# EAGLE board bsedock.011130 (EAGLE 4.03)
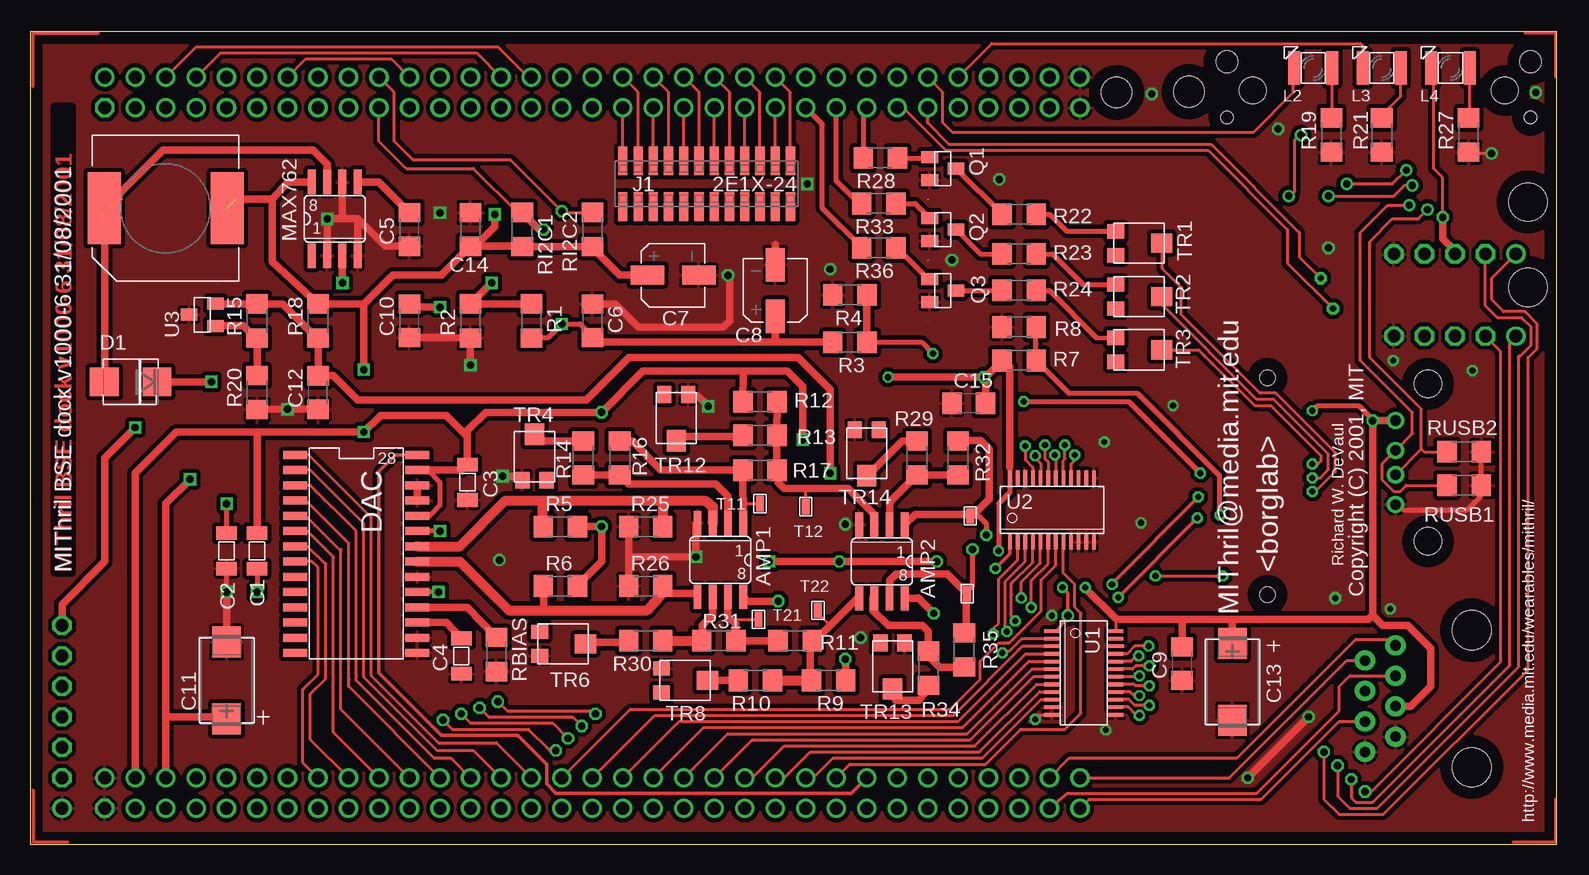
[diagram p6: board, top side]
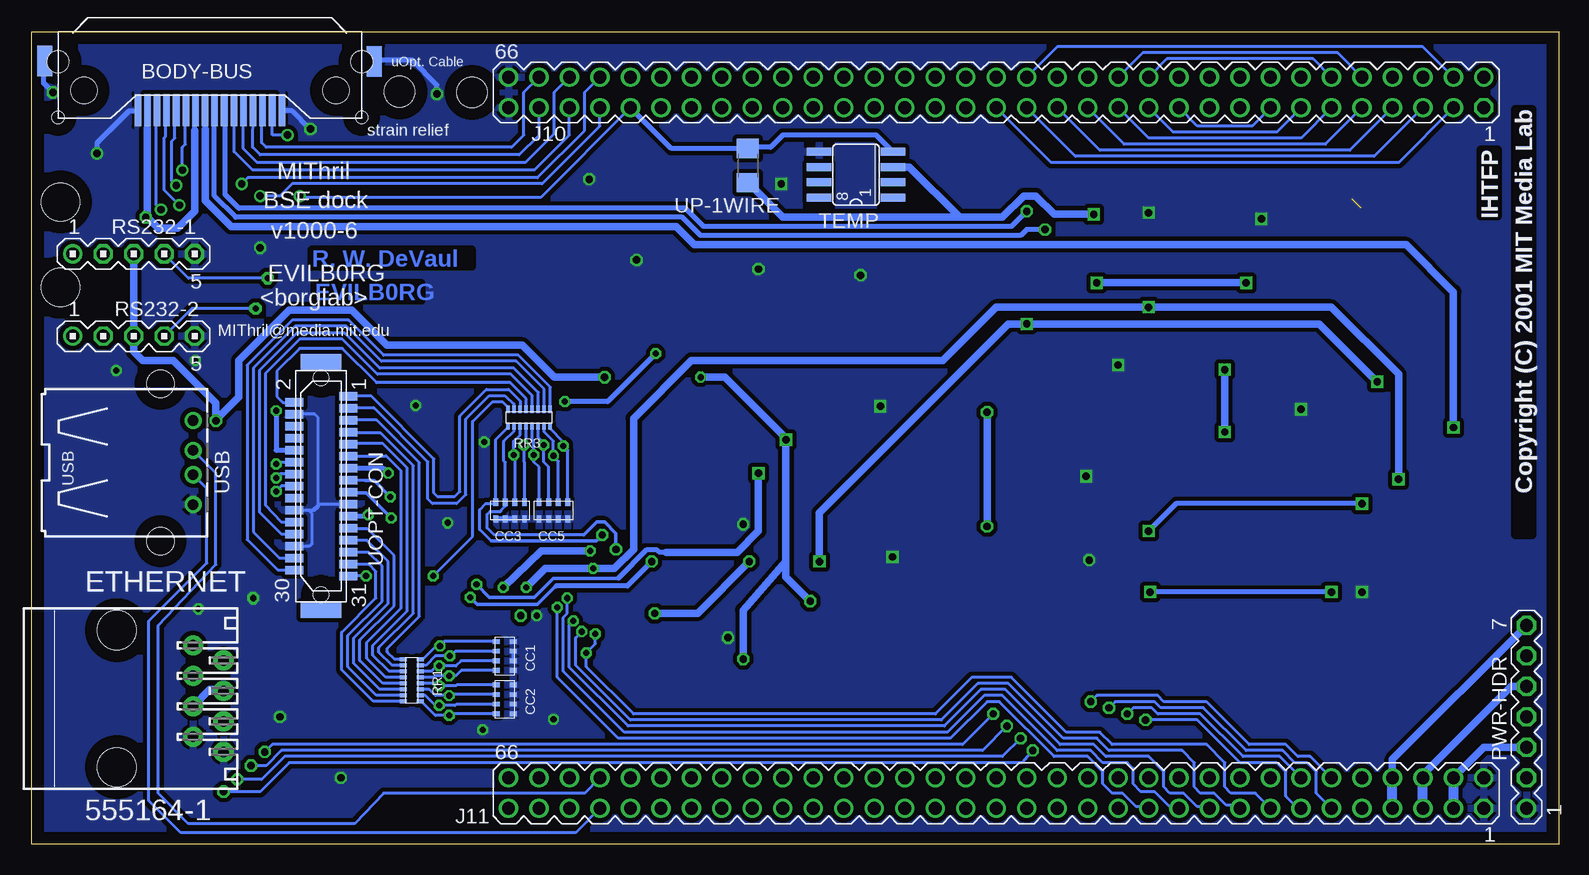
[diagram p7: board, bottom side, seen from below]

Size 127.23 x 67.74 mm. Coordinates in mm from the lower left corner, seen from the top.
Outline: 0,0 127.23,0 127.23,67.74 0,67.74 0,0
Copper layers used: Top, Bottom
Holes 3.17 mm at 124.84,46.44 124.84,53.56
Holes 2.54 mm at 90.55,62.7 96.58,62.76

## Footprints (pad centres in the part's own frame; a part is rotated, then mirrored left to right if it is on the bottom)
SO08 = smd 0.66 x 2.032: 1 -1.905,-3.073; 2 -0.635,-3.073; 3 0.635,-3.073; 4 1.905,-3.073; 5 1.905,3.073; 6 0.635,3.073; 7 -0.635,3.073; 8 -1.905,3.073
HRS3500 = smd 0.55 x 2.7: P$1 6,1.35; P$2 5.2,1.35; P$3 4.4,1.35; P$4 3.6,1.35; P$5 2.8,1.35; P$6 2,1.35; P$7 1.2,1.35; P$8 0.4,1.35; P$9 -0.4,1.35; P$10 -1.2,1.35; P$11 -2,1.35; P$12 -2.8,1.35; P$13 -3.6,1.35; P$14 -4.4,1.35; P$15 -5.2,1.35; P$16 -6,1.35 | smd 1.27 x 2.54: P_GND1 -13.7,-2.7; P_GND2 13.76,-2.74 | hole 2.2: -10.5,-0.3; 10.5,-0.3 | hole 1.8: -12.65,-2.7; 12.65,-2.7 | hole 1: -12.65,1.95; 12.65,1.95
1206 = smd 1.143 x 1.702: 1 -1.473,0; 2 1.473,0
C1206 = smd 1.6 x 1.8: 1 -1.4,0; 2 1.4,0
PAN-LY-C = smd 1.6 x 2.8: P+ 0,-2.15; P- 0,2.15
CT7343 = smd 2.6 x 2.4: 1 -3.2,0; 2 3.2,0
ECJRV = smd 0.4 x 0.6: P$1 -1.2,-0.7; P$2 -0.4,-0.7; P$3 0.4,-0.7; P$4 1.2,-0.7; P$5 1.2,0.7; P$6 0.4,0.7; P$7 -0.4,0.7; P$8 -1.2,0.7
SMB = smd 2.4 x 2.4: 1 -2.2,0; 2 2.2,0
SMD-28 = smd 0.66 x 2.007: 1 -8.89,-5.08; 2 -7.62,-5.08; 3 -6.35,-5.08; 4 -5.08,-5.08; 5 -3.81,-5.08; 6 -2.54,-5.08; 7 -1.27,-5.08; 8 0,-5.08; 9 1.27,-5.08; 10 2.54,-5.08; 11 3.81,-5.08; 12 5.08,-5.08; 13 6.35,-5.08; 14 7.62,-5.08; 15 7.62,5.08; 16 6.35,5.08; 17 5.08,5.08; 18 3.81,5.08; 19 2.54,5.08; 20 1.27,5.08; 21 0,5.08; 22 -1.27,5.08; 23 -2.54,5.08; 24 -3.81,5.08; 25 -5.08,5.08; 26 -6.35,5.08; 27 -7.62,5.08; 28 -8.89,5.08
555164-1 = drill 0.889 pad 1.676 round: 1 -4.445,5.207; 2 -3.175,7.747; 3 -1.905,5.207; 4 -0.635,7.747; 5 0.635,5.207; 6 1.905,7.747; 7 3.175,5.207; 8 4.445,7.747 | hole 3.251: -5.715,-1.143; 5.715,-1.143
2E1X-24 = smd 0.762 x 2.388: P$1 -7.62,1.905; P$2 -7.62,-1.905; P$3 -6.35,1.905; P$4 -6.35,-1.905; P$5 -5.08,1.905; P$6 -5.08,-1.905; P$7 -3.81,1.905; P$8 -3.81,-1.905; P$9 -2.54,1.905; P$10 -2.54,-1.905; P$11 -1.27,1.905; P$12 -1.27,-1.905; P$13 0,1.905; P$14 0,-1.905; P$15 1.27,1.905; P$16 1.27,-1.905; P$17 2.54,1.905; P$18 2.54,-1.905; P$19 3.81,1.905; P$20 3.81,-1.905; P$21 5.08,1.905; P$22 5.08,-1.905; P$23 6.35,1.905; P$24 6.35,-1.905
BSEHDR = drill 1.067 pad 1.6 octagon: 1 -41.91,-1.27 | drill 1.067 pad 1.6 round: 2 -41.91,1.27; 3 -39.37,-1.27; 4 -39.37,1.27; 5 -36.83,-1.27; 6 -36.83,1.27; 7 -34.29,-1.27; 8 -34.29,1.27; 9 -31.75,-1.27; 10 -31.75,1.27; 11 -29.21,-1.27; 12 -29.21,1.27; 13 -26.67,-1.27; 14 -26.67,1.27; 15 -24.13,-1.27; 16 -24.13,1.27; 17 -21.59,-1.27; 18 -21.59,1.27; 19 -19.05,-1.27; 20 -19.05,1.27; 21 -16.51,-1.27; 22 -16.51,1.27; 23 -13.97,-1.27; 24 -13.97,1.27; 25 -11.43,-1.27; 26 -11.43,1.27; 27 -8.89,-1.27; 28 -8.89,1.27; 29 -6.35,-1.27; 30 -6.35,1.27; 31 -3.81,-1.27; 32 -3.81,1.27; 33 -1.27,-1.27; 34 -1.27,1.27; 35 1.27,-1.27; 36 1.27,1.27; 37 3.81,-1.27; 38 3.81,1.27; 39 6.35,-1.27; 40 6.35,1.27; 41 8.89,-1.27; 42 8.89,1.27; 43 11.43,-1.27; 44 11.43,1.27; 45 13.97,-1.27; 46 13.97,1.27; 47 16.51,-1.27; 48 16.51,1.27; 49 19.05,-1.27; 50 19.05,1.27; 51 21.59,-1.27; 52 21.59,1.27; 53 24.13,-1.27; 54 24.13,1.27; 55 26.67,-1.27; 56 26.67,1.27; 57 29.21,-1.27; 58 29.21,1.27; 59 31.75,-1.27; 60 31.75,1.27; 61 34.29,-1.27; 62 34.29,1.27; 63 36.83,-1.27; 64 36.83,1.27; 65 39.37,-1.27; 66 39.37,1.27
D124C = smd 2.743 x 5.994: P$1 -5.131,0; P$2 5.131,0
L62711CT = smd 1 x 2.8: P$1 -1.6,0; P$2 1.6,0
MA07-1 = drill 1.067 pad 1.6 round: 1 -7.62,0 | drill 1.067 pad 1.6 octagon: 2 -5.08,0; 3 -2.54,0; 4 0,0; 5 2.54,0; 6 5.08,0; 7 7.62,0
SOT23 = smd 1 x 1.4: 1 -0.95,-1.1; 2 0.95,-1.1; 3 0,1.1
R1206 = smd 1.6 x 1.803: 1 -1.422,0; 2 1.422,0
EXB2HV = smd 0.294 x 0.6: P$1 -1.75,-0.7; P$2 -1.25,-0.7; P$3 -0.75,-0.7; P$4 -0.25,-0.7; P$5 0.25,-0.7; P$6 0.75,-0.7; P$7 1.25,-0.7; P$8 1.75,-0.7; P$9 1.75,0.7; P$10 1.25,0.7; P$11 0.75,0.7; P$12 0.25,0.7; P$13 -0.25,0.7; P$14 -0.75,0.7; P$15 -1.25,0.7; P$16 -1.75,0.7
MA05-1 = drill 1.067 pad 1.6 round: 1 -5.08,0 | drill 1.067 pad 1.6 octagon: 2 -2.54,0; 3 0,0; 4 2.54,0; 5 5.08,0
TEST = smd 0.66 x 1.27: P$1 0,0
P7JSMTPO = smd 1.194 x 1.397: 1 -1,-1.854; 3 1,-1.854 | smd 1.6 x 1.778: 2 0,1.98
QSOP24 = smd 0.305 x 1.27: P$1 0.838,-0.711; P$2 1.473,-0.711; P$3 2.108,-0.711; P$4 2.743,-0.711; P$5 3.378,-0.711; P$6 4.013,-0.711; P$7 4.648,-0.711; P$8 5.283,-0.711; P$9 5.918,-0.711; P$10 6.553,-0.711; P$11 7.188,-0.711; P$12 7.823,-0.711; P$13 7.823,4.623; P$14 7.188,4.623; P$15 6.553,4.623; P$16 5.918,4.623; P$17 5.283,4.623; P$18 4.648,4.623; P$19 4.013,4.623; P$20 3.378,4.623; P$21 2.743,4.623; P$22 2.108,4.648; P$23 1.473,4.623; P$24 0.838,4.623
DF9-31S = smd 0.7 x 1.5: 1 -7.5,2.25; 2 -7,-2.25; 3 -6.5,2.25; 4 -6,-2.25; 5 -5.5,2.25; 6 -5,-2.25; 7 -4.5,2.25; 8 -4,-2.25; 9 -3.5,2.25; 10 -3,-2.25; 11 -2.5,2.25; 12 -2,-2.25; 13 -1.5,2.25; 14 -1,-2.25; 15 -0.5,2.25; 16 0,-2.25; 17 0.5,2.25; 18 1,-2.25; 19 1.5,2.25; 20 2,-2.25; 21 2.5,2.25; 22 3,-2.25; 23 3.5,2.25; 24 4,-2.25; 25 4.5,2.25; 26 5,-2.25; 27 5.5,2.25; 28 6,-2.25; 29 6.5,2.25; 30 7,-2.25; 31 7.5,2.25 | smd 1.3 x 3.4: M1 -10.35,0; M2 10.35,0 | hole 1.27: 9.05,0; -9.05,0
USB = drill 0.889 pad 1.422 round: 1 -3.505,12.7; 2 -1.016,12.7; 3 1.016,12.7; 4 3.505,12.7 | hole 2.261: -6.566,9.982; 6.566,9.982

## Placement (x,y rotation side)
AMP1  AD8042AR  [SO08]  57.53,23.71 180 top
AMP2  EL2250CS  [SO08]  70.99,23.58 180 top
BODY-BUS  HRS3500R  [HRS3500]  112.39,62.57 180 bottom
C1  0.1uF  [1206]  18.92,24.47 90 top
C2  0.1uF  [1206]  16.38,24.47 270 top
C3  0.1uF  [1206]  36.44,30.19 270 top
C4  0.1uF  [1206]  35.94,15.71 270 top
C5  0.1uF  [C1206]  31.62,51.27 90 top
C6  0.1uF  [C1206]  46.86,43.65 270 top
C7  33uF  [PAN-LY-C]  53.59,47.46 270 top
C8  33uF  [PAN-LY-C]  62.1,46.19 0 top
C9  0.1uF  [C1206]  96.01,15.07 90 top
C10  0.1uF  [C1206]  31.62,43.65 90 top
C11  10uF  [CT7343]  16.38,13.68 90 top
C12  0.1uF  [C1206]  24,37.68 90 top
C13  10uF  [CT7343]  100.2,13.55 270 top
C14  0.1uF  [C1206]  36.7,51.27 270 top
C15  0.1uF  [C1206]  78.23,36.79 0 top
CC1  10pF  [ECJRV]  87.82,15.71 90 bottom
CC2  10pF  [ECJRV]  87.82,12.09 90 bottom
CC3  10pF  [ECJRV]  87.37,27.84 0 bottom
CC5  10pF  [ECJRV]  83.75,27.84 0 bottom
D1  MBRS130LT3  [SMB]  8.38,38.57 180 top
DAC  THS5641IDW  [SMD-28]  27.17,23.58 270 top
ETHERNET  555164-1  [555164-1]  118.99,12.15 270 bottom
J1  2E1X-24  [2E1X-24]  57.02,55.08 0 top
J10  BSEHDR  [BSEHDR]  48.13,62.7 0 top
J11  BSEHDR  [BSEHDR]  48.13,4.28 0 top
L1  [D124C]  11.3,53.05 180 top
L2  L628111CT-ND  [L62711CT]  106.93,64.73 0 top
L3  L628111CT-ND  [L62711CT]  112.64,64.73 0 top
L4  L628111CT-ND  [L62711CT]  118.36,64.73 0 top
MAX762  MAX762  [SO08]  25.39,52.16 0 top
PWR-HDR  MA07-1  [MA07-1]  2.66,10.63 90 bottom
Q1  2N7002  [SOT23]  76.07,56.35 270 top
Q2  2N7002  [SOT23]  76.07,51.27 270 top
Q3  2N7002  [SOT23]  76.07,46.19 270 top
R1  1.267M  [R1206]  41.78,43.65 270 top
R2  200K  [R1206]  36.7,43.65 90 top
R3  16.4k  [R1206]  68.32,41.87 180 top
R4  23.6k  [R1206]  68.32,45.81 0 top
R5  2.65k  [R1206]  44.19,26.51 0 top
R6  2.65k  [R1206]  44.19,21.55 0 top
R7  20K  [R1206]  82.42,40.35 180 top
R8  20K  [R1206]  82.42,43.14 0 top
R9  2.52k  [R1206]  66.54,13.68 0 top
R10  2.0k  [R1206]  60.45,13.68 0 top
R11  2.90k  [R1206]  63.75,16.98 180 top
R12  7.06k  [R1206]  60.83,36.92 180 top
R13  2.0k  [R1206]  60.83,34.12 0 top
R14  2k  [R1206]  46.1,32.22 270 top
R15  43k  [R1206]  18.92,43.65 90 top
R16  3.78k  [R1206]  49.14,32.22 90 top
R17  4.05k  [R1206]  60.83,31.2 180 top
R18  47k  [R1206]  24,43.65 90 top
R19  2.2k  [R1206]  108.45,59.14 90 top
R20  30k  [R1206]  18.92,37.68 90 top
R21  2.2k  [R1206]  112.64,59.14 90 top
R22  10 ohm  [R1206]  82.42,52.54 180 top
R23  10 ohm  [R1206]  82.42,49.24 180 top
R24  10 ohm  [R1206]  82.42,46.19 180 top
R25  49  [R1206]  51.3,26.51 0 top
R26  49  [R1206]  51.3,21.55 0 top
R27  2.2k  [R1206]  119.88,59.14 90 top
R28  10 ohm  [R1206]  70.86,57.24 180 top
R29  2k  [R1206]  73.91,32.22 270 top
R30  2k  [R1206]  51.3,16.98 0 top
R31  3.78k  [R1206]  57.4,16.98 0 top
R32  6.3k  [R1206]  77.34,32.22 90 top
R33  10 ohm  [R1206]  70.73,53.43 180 top
R34  2k  [R1206]  74.86,14.69 90 top
R35  6.3k  [R1206]  77.85,16.22 90 top
R36  10 ohm  [R1206]  70.73,49.75 180 top
RBIAS  2k  [R1206]  38.86,15.84 90 top
RI2C1  5k  [R1206]  41.02,51.27 270 top
RI2C2  5k  [R1206]  46.86,51.27 270 top
RR1  10  [EXB2HV]  95.56,13.68 90 bottom
RR3  10  [EXB2HV]  85.78,35.59 0 bottom
RS232-1  [MA05-1]  118.74,49.24 180 top
RS232-2  [MA05-1]  118.74,42.38 180 top
RUSB1  15K  [R1206]  119.5,29.93 180 top
RUSB2  15K  [R1206]  119.5,32.73 180 top
T1  TEST  [TEST]  60.83,28.41 0 top
T2  TEST  [TEST]  60.7,18.76 0 top
T3  TEST  [TEST]  65.65,19.52 0 top
T4  TEST  [TEST]  64.64,28.16 0 top
T5  TEST  [TEST]  78.35,27.39 0 top
T6  TEST  [TEST]  78.1,20.92 0 top
TEMP  DS1820  [SO08]  58.54,55.84 90 bottom
TR1  200 POT  [P7JSMTPO]  92.32,50.13 270 top
TR2  200 POT  [P7JSMTPO]  92.32,45.68 270 top
TR3  200 POT  [P7JSMTPO]  92.32,41.24 270 top
TR4  200 POT  [P7JSMTPO]  42.03,32.22 0 top
TR6  200 POT  [P7JSMTPO]  44.32,16.73 270 top
TR8  200 POT  [P7JSMTPO]  54.48,13.68 270 top
TR12  200 POT  [P7JSMTPO]  53.84,35.65 180 top
TR13  200 POT  [P7JSMTPO]  71.88,14.95 180 top
TR14  200 POT  [P7JSMTPO]  69.72,32.73 180 top
U1  74LVX3245QSCF  [QSOP24]  85.85,18.63 270 top
U2  74LVX3245QSCF  [QSOP24]  80.83,25.93 0 top
U3  [SOT23]  14.35,44.16 90 top
UOPT-CON  DF9-31P-1V  [DF9-31S]  103.12,29.87 270 bottom
UP-1WIRE  5k  [R1206]  67.56,56.6 270 bottom
USB  USB-87531  [USB]  126.49,31.84 270 bottom

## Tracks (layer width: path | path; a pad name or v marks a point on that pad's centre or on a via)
1WIRE  (via drill 0.61 pad 1.02)
  Top 0.254: v105.91,59.14 105.79,59.14 105.41,58.76 105.41,54.45 105.02,54.06 v104.9,54.06
  Bottom 0.254: v105.91,59.14 107.18,59.14 BODY-BUS.P$15 | v104.9,54.06 105.02,53.94 84.83,53.94 J10.57
  Bottom 0.406: J10.57 73.93,58.03 UP-1WIRE.1 67.46,58.13 65.65,58.13 64.64,59.14 56.87,59.14 TEMP.4
+2V  (via drill 0.51 pad 0.3, 0.61 pad 1.02)
  Top 0.305: v97.34,28.98 90.17,21.74 v90.17,21.68
  Top 0.61: v66.67,30.95 66.67,37.93 64,40.6 49.91,40.6 46.35,37.05 27.3,37.05 25.27,39.08 C12.2 R18.1 23.9,42.23 21.08,45.05 18.92,45.05 R15.2 18.89,45.05 15.49,45.05 15.49,45.06 U3.2
  Bottom 0.305: 78.35,22.19 83.75,22.19 85.34,20.6 89.09,20.6 v90.17,21.68 | UOPT-CON.15 99.44,30.34 98.7,30.34 v97.34,28.98
  Bottom 0.406: 74.35,24.35 74.92,24.35 75.12,24.54 76.01,24.54 78.35,22.19
  Bottom 0.61: v66.67,30.95 66.67,26.12 68.45,24.35 74.35,24.35
+3V  (via drill 0.51 pad 0.3, 0.61, 0.61 pad 1.02)
  Top 0.254: 81.66,25.23 U2.P$1
  Top 0.305: U1.P$1 85.58,17.79 v86.48,19.08 86.48,20.98 v86.04,21.42 | v80.45,23.01 81.66,24.22 81.66,25.23
  Top 0.61: J11.6 11.3,10.63 | 11.3,10.63 11.3,28.41 v13.33,30.44 | v34.16,44.79 32.76,44.79 C10.2 | C11.1 16.38,10.63 11.3,10.63
  Bottom 0.61: v13.33,30.44 13.33,39.2 18.92,44.79 v34.16,44.79 46.86,44.79 51.3,40.35 72.26,40.35 77.08,35.52 77.08,24.6 78.67,23.01 v80.45,23.01 84.45,23.01 v86.04,21.42 | PWR-HDR.5 3.93,13.17 11.3,5.8 J11.6
  Bottom 0.813: J11.5 J11.6
+5V  (via drill 0.51 pad 0.3, 0.61, 0.61 pad 1.02)  (1 unrouted)
  Top 0.254: 116.84,64.66 L4.P$1 116.76,64.28 116.71,64.22 116.71,64.48 116.96,64.22 116.96,56.35 117.72,55.59 v117.72,52.29 | v87.94,21.42 87.94,21.36 | 90.47,18.83 U1.P$24 | 81.66,30.57 U2.P$24 | RS232-1.3 118.74,49.49
  Top 0.305: 81.02,40.35 81.02,40.48 81.66,39.84
  Top 0.406: DAC.24 33.27,27.39 34.16,28.28 34.16,30.19 33.14,31.2 DAC.27 32.13,31.2 | 81.66,31.46 81.66,30.57 81.66,29.36 80.7,28.41 v80.7,24.47 | v106.87,36.16 107.25,36.54 110.75,36.54 111.88,35.41 111.9,35.39 | 90.8,18.76 90.55,18.76
  Top 0.61: ETHERNET.5 115.06,11.52 116.71,13.17 116.71,16.34 114.8,18.25 112.71,18.25 111.88,19.08 111.88,19.14 | 59.43,39.46 51.05,39.46 v47.62,36.03 37.97,36.03 36.44,34.51 36.44,34 | 59.43,39.46 63.11,39.46 64.38,38.19 v64.38,33.74 | 18.92,34.38 v27.81,34.38 29.2,35.78 34.67,35.78 36.44,34 | C14.2 34.28,47.46 30.22,47.46 27.81,45.05 | 27.81,45.05 24,45.05 | MAX762.8 23.52,55.21 21.46,55.21 20.19,53.81 | C14.2 39.11,49.87 40.25,49.87 RI2C1.2 RI2C2.2 | R5.2 v47.62,26.51 47.62,23.58 R6.2 | 59.43,39.46 R12.2 | R9.2 68.07,13.14 v67.94,15.46 | RI2C2.2 46.86,49.87 | 24,45.05 R18.2 | 24,45.05 20.19,48.6 20.19,53.81 | 20.19,53.81 17.19,53.81 | DAC.27 35.94,31.2 36.44,31.71 C3.1 36.44,34 | J11.4 8.76,30.95 12.19,34.38 18.92,34.38 | v27.81,39.59 27.81,45.05 | 18.92,34.38 C1.2 | RI2C2.2 46.86,49.75 49.14,47.46 C7.P+ | v38.73,52.54 38.73,51.52 37.21,50 36.7,50 C14.2 | v117.72,52.29 117.72,50.51 118.74,49.49 | v62.35,20.28 59.56,20.28 59.56,20.54 59.46,20.64 AMP1.8 | R7.2 81.02,40.35 79.62,38.95 v79.5,38.95 | v71.5,38.95 v79.5,38.95 | 81.66,39.84 81.66,31.46 | 111.88,33.36 111.88,19.14 | 111.88,33.36 111.88,33.38 | v111.88,35.33 111.88,33.36 | v111.88,35.33 111.88,35.41 | USB.1 v111.88,35.33 | C15.2 79.63,38.82 v79.5,38.95 | 100.2,18.76 C13.1 | 96.01,18.76 C9.2 | 100.2,18.76 111.5,18.76 111.88,19.14 | 87.94,21.36 90.47,18.83 | 96.01,18.76 90.8,18.76 | 100.2,18.76 96.01,18.76
  Bottom 0.254: v64.38,33.74 64.32,33.81
  Bottom 0.406: 117.6,59.71 BODY-BUS.P$2 | v117.72,52.29 117.6,52.29 | BODY-BUS.P$7 113.64,61.18 113.66,61.18 113.66,59.52 | UOPT-CON.10 106.72,32.87 106.87,32.85 v106.87,36.16
  Bottom 0.61: v64.38,33.74 64.38,23.58 | v27.81,34.38 v27.81,39.59 | v47.62,36.03 v47.62,26.51 | 117.6,59.71 117.6,52.29 116.71,51.4 115.06,51.4 113.66,52.79 113.66,59.52 | v67.94,15.46 67.94,19.52 64.38,23.58 | v38.73,52.54 42.03,52.54 43.56,54.06 44.57,54.06 46.35,52.29 49.91,52.29 | 49.91,52.29 64.64,52.29 67.43,55.08 67.46,55.08 UP-1WIRE.2 | ETHERNET.4 111.37,12.92 112.39,12.92 ETHERNET.5 | RS232-1.3 RS232-2.3 118.74,41.11 117.98,40.35 115.44,40.35 111.88,36.79 111.88,35.39 | 64.38,23.58 64.38,22.31 v62.35,20.28 | TEMP.3 54.1,56.48 49.91,52.29 | J11.4 6.22,8.09 PWR-HDR.3 | v80.7,24.47 84.77,24.47 v87.94,21.42 | v71.5,38.95 69.46,38.95 64.32,33.81 | 111.88,35.39 v111.88,35.33 | v79.5,38.95 83.69,38.95 86.36,41.62 97.66,41.62 100.58,44.54 105.79,44.54 109.98,40.35 109.98,37.3 111.88,35.39
  Bottom 0.813: J11.4 J11.3
+6.5VREF  (via drill 0.51 pad 0.3)
  Top 0.406: R3.1 74.29,41.87 v75.24,40.92 | v82.8,36.92 91.56,36.92 v97.53,30.95
  Top 0.61: R3.1 R4.2
  Bottom 0.406: 75.18,40.98 v75.24,40.92 79.24,36.92 v82.8,36.92 | UOPT-CON.13 100.83,31.33 97.91,31.33 v97.53,30.95
+11V  (via drill 0.51 pad 0.3, 0.61, 0.61 pad 1.02)
  Top 0.305: v90.67,20.6 v97.28,27.2
  Top 0.406: C6.2 46.86,42.38 45.84,43.4 v44.32,43.4 43.15,42.23 R1.2
  Top 0.61: D1.1 v15.11,38.57 | 62.1,41.87 C8.P+ | 62.1,41.87 R3.2 | C6.2 47.24,41.87 62.1,41.87 | v75.56,23.58 v67.43,23.58 v61.59,23.58 | v75.31,19.27 74.04,20.54 74.01,20.51 AMP2.8
  Bottom 0.305: 83.56,21.55 85.09,20.03 90.1,20.03 v90.67,20.6 | UOPT-CON.17 100.32,29.37 100.33,29.36 100.26,29.3 99.37,29.3 v97.28,27.2
  Bottom 0.406: v75.56,23.58 77.59,21.55 83.56,21.55
  Bottom 0.61: v61.59,23.58 61.59,27.65 45.84,43.4 v44.32,43.4 19.93,43.4 v15.11,38.57 | v75.31,19.27 71.75,19.27 v67.43,23.58
BLINKY1
  Top 0.254: L3.P$1 111.04,66.59 110.87,66.76 80.13,66.76 J10.58
BLINKY2
  Top 0.254: J10.56 76.07,62.7 76.07,60.16 76.83,59.4 101.98,59.4 105.28,62.7 105.28,64.68 L2.P$1
BSE_B
  Top 0.406: R28.2 69.46,57.24 69.46,61.18 J10.51
BSE_G
  Top 0.406: R33.2 69.08,53.43 67.18,55.33 J10.49
BSE_INIT
  Top 0.254: J11.50 68.32,6.69 79.62,6.69 82.55,9.61 86.23,9.61 87.56,10.95 87.56,19.27 87.05,19.77 87.05,21.68 86.11,22.62 U2.P$8 86.1,25.23
BSE_PDR
  Top 0.254: J11.32 50.03,11.27 76.7,11.27 79.18,13.74 79.18,15.27 80.7,16.79 81.59,16.79 84.26,19.46 84.26,20.09 | 85.47,25.23 U2.P$7 85.48,23.28 84.26,22.06 84.26,20.09 | 84.26,20.09 84.26,20.16
BSE_R
  Top 0.406: J10.47 66.03,60.03 66.03,53.05 69.34,49.75 R36.2
BSEDCIN  (via drill 0.61 pad 1.02)
  Top 0.61: v8.76,34.76 6.22,32.22 6.22,23.58 2.66,20.03 PWR-HDR.7
  Bottom 0.406: 112.77,59.65 112.79,61.2 BODY-BUS.P$8
  Bottom 0.61: v8.76,34.76 8.76,46.06 12.7,50 72,50 73.53,51.52 110.61,51.52 112.77,53.68 112.77,59.65 | PWR-HDR.7 13.84,7.07 J11.8
  Bottom 0.813: J11.7 J11.8
DAC0
  Top 0.254: DAC.8 23.49,23.58 24,23.08 24,14.19 22.73,12.92 22.73,6.82 J11.16
DAC1
  Top 0.254: 24.63,23.33 22.98,24.98 22.22,24.98 DAC.7 | J11.18 23.36,8.72 23.36,12.54 24.63,13.8 24.63,23.33 | 24.63,23.33 24.63,23.46
DAC2
  Top 0.254: J11.20 25.27,9.36 25.27,23.96 23.11,26.12 DAC.6
DAC3
  Top 0.254: 25.9,24.47 22.98,27.39 DAC.5 | 25.9,24.47 25.9,24.6 | J11.22 25.9,11.27 25.9,24.47
DAC4
  Top 0.254: 26.54,13.8 26.54,25.11 22.98,28.66 DAC.4 21.84,28.66 | 26.54,13.8 26.54,13.68 | J11.24 26.54,13.17 26.54,13.8
DAC5
  Top 0.254: J11.26 35.05,7.2 33.65,7.2 27.17,13.68 27.17,14.19 | 27.17,14.19 27.17,26.12 23.36,29.93 22.22,29.93 22.09,30.06 DAC.3 | 27.17,14.19 27.17,14.06
DAC6
  Top 0.254: J11.28 36.95,7.84 33.9,7.84 27.81,13.93 27.81,26.76 23.36,31.2 DAC.2
DAC7
  Top 0.254: J11.30 38.86,8.47 34.03,8.47 28.44,14.06 28.44,27.27 23.24,32.47 DAC.1 21.97,32.47
DAC_CLK
  Top 0.305: J11.52 68.45,4.28 43.81,4.28 43.05,5.04 43.05,6.69 40.64,9.11 34.28,9.11 29.08,14.31 29.08,31.08 30.48,32.47 DAC.28 32.51,32.47
EXP_1  (via drill 0.61 pad 1.02)
  Top 0.254: v108.2,54.06 113.66,54.06 114.55,54.95 v115.18,54.95
  Bottom 0.254: J10.59 79.88,59.91 84.7,55.08 105.53,55.08 106.55,54.06 v108.2,54.06 | v115.18,54.95 115.56,55.33 115.56,58.64 115.31,58.89 115.31,61.1 BODY-BUS.P$5
EXP_2  (via drill 0.61 pad 1.02)
  Top 0.254: v109.72,55.08 113.53,55.08 v114.68,56.22
  Bottom 0.254: J10.60 81.15,62.7 81.15,59.52 85.09,55.59 109.22,55.59 v109.72,55.08 | BODY-BUS.P$6 114.42,61.18 114.42,58.38 114.68,58.13 v114.68,56.22
EXP_3
  Bottom 0.254: J10.61 82.42,59.14 85.34,56.22 108.83,56.22 110.36,57.75 110.36,58.89 BODY-BUS.P$11
EXP_4
  Bottom 0.254: J10.62 83.69,62.7 83.69,59.27 86.1,56.86 108.45,56.86 109.6,58 109.6,61.18 BODY-BUS.P$12
EXP_5
  Bottom 0.254: J10.63 84.96,59.14 86.61,57.49 108.2,57.49 108.83,58.13 BODY-BUS.P$13
EXP_6
  Bottom 0.254: J10.64 86.23,62.7 86.23,59.14 87.24,58.13 107.69,58.13 108.07,58.51 108.07,61.18 BODY-BUS.P$14
FEXT0
  Top 0.254: J1.P$1 J10.35
FEXT1
  Top 0.254: J1.P$3 50.67,62.7 J10.36
FEXT2
  Top 0.254: J1.P$5 J10.37
FEXT3
  Top 0.254: J1.P$7 53.21,62.7 J10.38
FEXT4
  Top 0.254: J1.P$9 J10.39
FEXT5
  Top 0.254: J1.P$11 55.75,62.7 J10.40
FEXT6
  Top 0.254: J1.P$13 J10.41
FEXT7
  Top 0.254: J1.P$15 58.29,62.7 J10.42
FEXT8
  Top 0.254: J1.P$17 J10.43
FEXT9
  Top 0.254: J1.P$19 60.83,62.7 J10.44
FEXT10
  Top 0.254: J1.P$21 J10.45
FEXT11
  Top 0.254: J1.P$23 63.37,62.7 J10.46
GND1  (via drill 0.51 pad 0.3, 0.51 pad 1.02, 0.61, 0.61 pad 1.02)
  Top 0.254: R27.1 119.98,57.62 v121.79,57.62 | U1.P$12 84.12,10.81 v83.75,10.44
  Top 0.406: v16.38,21.04 C2.2 | C3.2 36.44,28.66 | R19.1 108.45,57.75 | R21.1 112.64,57.87 112.52,57.75 | RUSB1.1 RUSB2.1 | RUSB1.1 120.92,29.83 120.77,29.68 | RUSB1.1 120.92,29.07 119.76,27.9 114.42,27.9 113.91,28.41 113.84,28.33 USB.4
  Top 0.61: MAX762.2 v24.76,52.16 26.03,52.16 | 26.03,52.16 MAX762.6 | 74.9,45.17 Q3.2 74.92,45.17 | 27.3,52.16 MAX762.4 | MAX762.2 24.76,48.98 | MAX762.2 24.76,50.51 | v101.47,5.55 v106.55,10.63 | AMP1.4 55.49,26.66 v55.49,23.96 49.91,23.96 | TR4.1 40.31,30.7 v39.36,30.7 | 42.41,15.67 TR6.3 | TR12.1 55.61,37.41 v56.51,36.54 | DAC.25 DAC.26 | 26.03,52.16 27.3,52.16 | R20.1 v21.46,36.28 C12.1 | R26.1 49.91,23.96 | 49.91,23.96 R25.1 | v36.7,39.97 R2.1 34.16,42.25 C10.1 | 46.98,44.92 C6.1 48.76,45.05 50.67,43.14 57.78,43.14 58.29,43.65 58.29,47.46 v58.16,47.46 | 27.3,52.16 29.59,49.87 C5.1 | 16.38,16.85 C11.2 v16.38,21.04 | R4.1 66.92,45.81 | C8.P- 62.1,50 | AMP2.4 69.08,27.27 | 76.56,48.73 v76.83,48.73 76.96,48.73
  Bottom 0.254: 118.44,61.18 BODY-BUS.P$1 | 106.29,61.13 106.25,61.18 | UOPT-CON.4 103.66,35.87 103.37,35.59 103.37,28.35 | 103.37,28.35 103.37,28.16 103.69,27.84 104.14,27.84 | UOPT-CON.19 100.89,28.35 103.37,28.35 | 103.37,28.35 103.88,27.84 104.14,27.84 | 104.14,27.84 105.34,27.84 UOPT-CON.20 105.34,27.84 104.14,27.84 | 104.14,27.84 103.88,27.59 103.88,25.05 104.07,24.85 105.35,24.85 UOPT-CON.26 | CC1.P$2 87.12,15.27 | CC1.P$2 | CC1.P$3 CC1.P$2
  Bottom 0.406: v24.76,52.16 25.01,51.91 25.01,52.16 | BODY-BUS.P$1 118.31,61.22 | BODY-BUS.P$16 106.29,61.13 106.29,61.18 105.53,61.18 v104.01,59.65 | 87.75,27.14 CC3.P$2 | 87.75,27.14 CC3.P$1 | 87.75,27.14 | CC3.P$3 86.99,27.14 87.75,27.14 | v93.47,62.57 93.47,63.34 95.5,65.37 98.55,65.37 98.67,65.24 98.69,65.26 BODY-BUS.P_GND1 | BODY-BUS.P_GND2 126.2,65.37 126.23,65.37 126.23,63.46 v125.47,62.7 | 118.44,61.18 119.12,61.18 121.79,58.51 v121.79,57.62
  other vias: 34.16,52.67 66.67,47.97 64.77,55.08 108.77,20.54 69.21,17.23 67.94,26.7 39.11,23.71 85.15,19.08 95.25,36.6 120.2,39.52 113.6,40.35 113.34,19.65 92.58,26.82 89.53,33.55 89.66,9.55 80.77,55.46 108.2,49.75
  pour Bottom (isolate 0.356): 0.25,67.53 126.87,67.53 126.87,0.34 0.25,0.34
  pour Top (isolate 0.356): 0.25,67.65 127.12,67.65 127.12,0.09 0.25,0.09
HCK
  Bottom 0.254: RR1.P$14 98.24,12.93 100.39,15.07 100.39,17.23 97.53,20.09 97.53,23.58 99.31,25.36 100.33,25.36
  Bottom 0.305: 100.33,25.36 100.32,25.37 UOPT-CON.25
HLTOR
  Bottom 0.254: 100.27,32.35 97.72,32.35 97.72,32.41 96.45,31.14 96.45,19.71 99.31,16.85 99.31,15.52 97.72,13.93 RR1.P$12
  Bottom 0.305: 100.27,32.35 UOPT-CON.11
HODL
  Bottom 0.254: RR1.P$11 97.45,14.43 98.8,15.77 98.8,16.6 95.94,19.46 95.94,31.39 97.98,33.43 100.33,33.43 100.3,33.4 UOPT-CON.9
HPL
  Bottom 0.254: RR1.P$13 97.98,13.43 99.88,15.33 | 100.33,26.31 99.25,26.31 97.02,24.09 97.02,19.9 99.88,17.04 99.88,15.33 | 99.88,15.33 99.88,15.27
  Bottom 0.305: 100.33,26.31 100.3,26.34 UOPT-CON.23
HSYNC
  Top 0.254: J10.22 30.09,65.49 22.98,65.49 J10.14
I2CSCL  (via drill 0.61 pad 1.02)
  Top 0.254: RI2C2.1 45.72,52.67 44.44,52.67 v44.32,52.79 40,57.11 31.87,57.11 30.35,58.64 30.35,62.7 J10.20
  Bottom 0.406: BODY-BUS.P$10 111.19,61.12 111.12,61.05 111.12,54.19 109.98,53.05 72.77,53.05 71.24,51.52 45.59,51.52 v44.32,52.79
I2CSDA  (via drill 0.61 pad 1.02)
  Top 0.254: RI2C1.1 40.64,52.67 36.95,56.35 31.36,56.35 29.08,58.64 J10.19
  Top 0.61: RI2C1.1 41.14,52.54 42.41,51.27 v42.79,51.27
  Bottom 0.406: v42.79,51.27 44.32,51.27 44.83,50.76 71.5,50.76 73.02,52.29 110.23,52.29 112.01,54.06 112.01,61.05 111.99,61.16 BODY-BUS.P$9
I_HCK  (via drill 0.51 pad 0.3)
  Top 0.254: U1.P$16 91.7,12.71 92.01,12.41 v92.45,12.41
  Bottom 0.254: RR1.P$3 94.11,12.93 93.59,12.41 v92.45,12.41 92.45,12.47 92.43,12.49 CC2.P$6
I_HLTOR  (via drill 0.51 pad 0.3)
  Top 0.254: U1.P$18 92.38,13.98 v92.45,14.06
  Bottom 0.254: RR1.P$5 93.72,13.93 93.59,14.06 v92.45,14.06 91.88,14.06 91.43,14.51 CC1.P$8
I_HODL  (via drill 0.51 pad 0.3)
  Top 0.254: U1.P$19 90.53,14.62 90.55,14.63 91.88,14.63 92.13,14.88 v93.28,14.88
  Bottom 0.254: RR1.P$6 93.92,14.43 93.47,14.88 93.34,14.88 | 93.34,14.88 v93.28,14.88 91.88,14.88 91.45,15.31 CC1.P$7 | 93.34,14.88 93.4,14.88
I_HPL  (via drill 0.51 pad 0.3)
  Top 0.254: v93.28,13.23 92.13,13.23 92.01,13.36 90.55,13.36 90.53,13.35 U1.P$17
  Bottom 0.254: RR1.P$4 93.47,13.43 v93.28,13.23 91.88,13.23 91.82,13.29 CC2.P$5
I_INIT  (via drill 0.51 pad 0.3)
  Top 0.254: U2.P$16 86.75,30.49 86.74,30.51 86.74,30.54 U2.P$16 | U2.P$16 86.75,31.73 87.05,32.03 v87.05,32.47
  Bottom 0.254: RR3.P$3 86.53,34.14 87.05,33.62 v87.05,32.47 86.97,32.45 CC3.P$6
I_PDR  (via drill 0.51 pad 0.3)
  Top 0.254: v86.23,33.3 86.23,32.16 86.1,32.03 86.1,30.57 U2.P$17 86.11,30.49
  Bottom 0.254: RR3.P$4 86.03,33.49 v86.23,33.3 86.23,31.9 86.17,31.84 CC3.P$5
I_RENE  (via drill 0.51 pad 0.3)
  Top 0.254: U1.P$15 91.58,12.08 92.07,11.58 v93.28,11.58
  Bottom 0.254: RR1.P$2 94.44,12.43 93.59,11.58 v93.28,11.58 91.94,11.58 91.84,11.69 CC2.P$7
I_RENO  (via drill 0.51 pad 0.3)
  Top 0.254: v92.45,10.76 92.2,10.76 91.5,11.46 90.48,11.46 U1.P$14
  Bottom 0.254: RR1.P$1 94.77,11.93 93.59,10.76 v92.45,10.76 92.39,10.76 92.25,10.89 CC2.P$8
I_TEST1  (via drill 0.51 pad 0.3)
  Top 0.254: U2.P$21 83.57,31.45 82.93,32.09 v82.93,33.24 | U2.P$21 83.57,30.49 83.56,30.51 83.56,30.54 U2.P$21
  Bottom 0.254: RR3.P$8 84.03,34.66 82.93,33.55 v82.93,33.24 82.55,32.86 CC5.P$5
I_TEST2  (via drill 0.51 pad 0.3)
  Top 0.254: U2.P$20 84.21,31.76 83.75,32.22 v83.75,32.41 | U2.P$20 84.21,30.49 84.2,30.51 84.2,30.54 U2.P$20
  Bottom 0.254: RR3.P$7 84.52,34.88 84.51,34.89 84.51,34.38 83.75,33.62 v83.75,32.41 83.75,32.35 83.35,31.95 CC5.P$6
I_TEST3  (via drill 0.51 pad 0.3)
  Top 0.254: 84.84,30.49 U2.P$19 84.83,30.57 84.83,31.9 84.58,32.16 v84.58,33.3
  Bottom 0.254: RR3.P$6 85.03,33.95 84.58,33.49 84.58,33.36 | 84.58,33.36 v84.58,33.3 84.58,31.9 84.15,31.48 CC5.P$7 | 84.58,33.36 84.58,33.43
I_TEST4  (via drill 0.51 pad 0.3)
  Top 0.254: U2.P$18 85.48,32.4 v85.4,32.47 | U2.P$18 85.48,30.49 85.47,30.51 85.47,30.54 U2.P$18
  Bottom 0.254: RR3.P$5 85.53,33.74 85.4,33.62 v85.4,32.47 85.4,31.9 84.95,31.45 CC5.P$8
I_VCK  (via drill 0.51 pad 0.3)
  Top 0.254: U1.P$21 91.42,15.89 92.07,16.54 v93.21,16.54
  Bottom 0.254: RR1.P$8 94.64,15.43 93.53,16.54 v93.21,16.54 92.84,16.91 CC1.P$5
I_VPL  (via drill 0.51 pad 0.3)
  Top 0.254: U1.P$20 91.74,15.25 92.2,15.71 v92.39,15.71
  Bottom 0.254: RR1.P$7 94.86,14.95 94.36,14.95 93.59,15.71 v92.39,15.71 92.32,15.71 91.92,16.11 CC1.P$6
INIT
  Bottom 0.254: UOPT-CON.1 98.94,37.37 93.72,32.16 93.72,29.3 93.4,28.98 92.01,28.98 91.56,29.43 91.56,35.71 89.34,37.93 87.5,37.93 86.53,36.97 RR3.P$14
IOUT1
  Top 0.61: 42.67,26.53 R5.1
  Top 0.813: DAC.22 35.81,24.85 39.62,28.66 42.67,28.66 | 42.67,28.66 52.7,28.66 | 52.7,28.66 56.26,28.66 56.89,28.16 AMP1.3 | 42.67,28.66 42.67,26.53 | R25.2 52.72,27.55 52.7,28.66
IOUT2
  Top 0.406: 55.52,20.64 AMP1.5 55.62,20.79 | 55.49,20.92 55.62,20.92
  Top 0.61: 42.79,19.52 R6.1 | 55.62,20.92 55.62,20.79 55.49,20.92 52.7,20.92
  Top 0.813: DAC.21 35.81,23.58 39.87,19.52 42.79,19.52 51.43,19.52 52.7,20.92 R26.2
K_HCK
  Top 0.254: J11.44 60.19,5.55 62.86,8.22 78.73,8.22 83.88,13.36 85,13.36 U1.P$8
K_HLTOR
  Top 0.254: J11.40 58.16,9.23 78.1,9.23 83.5,14.63 U1.P$6
K_HODL
  Top 0.254: J11.38 56.13,9.74 77.72,9.74 83.24,15.27 84.81,15.27 U1.P$5
K_HPL
  Top 0.254: J11.42 60.19,8.72 78.35,8.72 83.62,14 85.25,14 U1.P$7
K_LEDB  (via drill 0.51 pad 0.3)
  Top 0.254: 94.36,50.07 94.36,48.03 95.94,46.44 95.94,44.16 102.48,37.62 103.82,37.62 108.77,32.66 108.77,31.08 107.12,29.43 v106.87,29.43
  Top 0.406: 94.36,50.07 TR1.2
  Bottom 0.254: 105.34,29.87 UOPT-CON.16 106.42,29.87 v106.87,29.43
K_LEDG  (via drill 0.51 pad 0.3)
  Top 0.254: TR2.2 94.3,45.03 102.23,37.11 103.63,37.11 108.2,32.54 108.2,31.27 107.5,30.57 v106.87,30.57
  Bottom 0.254: UOPT-CON.14 106.56,30.87 v106.87,30.57
K_LEDR  (via drill 0.51 pad 0.3)
  Top 0.254: v106.87,31.71 107.31,31.71 107.56,31.97 107.56,32.41 103.37,36.6 102.04,36.6 97.4,41.24 TR3.2
  Bottom 0.254: UOPT-CON.12 106.71,31.87 v106.87,31.71
K_RENE
  Top 0.254: J11.46 62.86,5.55 65.02,7.71 79.12,7.71 84.13,12.73 85.28,12.73 85.16,12.71 U1.P$9
K_RENO
  Top 0.254: J11.48 65.27,5.55 66.92,7.2 79.37,7.2 84.26,12.09 85.28,12.09 85.16,12.08 U1.P$10
K_TEST1  (via drill 0.51 pad 0.3)
  Top 0.254: v81.4,17.74 81.28,17.87 81.28,21.93 82.93,23.58 82.93,25.21 U2.P$3
  Bottom 0.254: J11.17 26.79,3.26 27.68,3.26 28.7,4.28 29.84,4.28 30.35,4.79 30.35,6.82 31.36,7.84 37.46,7.84 38.48,8.85 41.27,8.85 45.84,13.42 48.38,13.42 51.43,10.38 77.34,10.38 81.91,14.95 81.91,17.23 v81.4,17.74
K_TEST2  (via drill 0.51 pad 0.3)
  Top 0.254: v82.1,18.63 81.78,19.01 81.78,20.79 | U2.P$4 83.56,25.21 83.56,23.52 81.78,21.74 81.78,20.79 | 81.78,20.79 81.78,20.85
  Bottom 0.254: J11.19 29.2,3.14 30.09,3.14 31.24,4.28 32.38,4.28 32.89,4.79 32.89,6.06 34.16,7.33 37.71,7.33 38.73,8.34 41.52,8.34 46.1,12.92 48.13,12.92 51.18,9.87 77.53,9.87 82.42,14.76 82.42,18.31 v82.1,18.63
K_TEST3  (via drill 0.51 pad 0.3)
  Top 0.254: U2.P$5 84.21,25.29 84.2,25.3 84.2,23.46 82.61,21.87 v82.61,20.54
  Bottom 0.254: J11.21 32.25,3.01 33.65,4.41 34.79,4.41 35.43,5.04 35.43,6.31 35.94,6.82 37.97,6.82 38.98,7.84 41.78,7.84 46.35,12.41 47.87,12.41 50.92,9.36 77.85,9.36 82.93,14.44 82.93,18.95 82.61,19.27 v82.61,20.54
K_TEST4  (via drill 0.51 pad 0.3)
  Top 0.254: 84.83,25.23 U2.P$6 84.84,23.41 83.43,22 v83.43,19.77
  Bottom 0.254: J11.23 34.03,3.14 35.17,3.14 36.32,4.28 37.21,4.28 37.97,5.04 37.97,6.06 39.24,7.33 42.03,7.33 46.6,11.9 47.62,11.9 50.67,8.85 78.35,8.85 83.43,13.93 v83.43,19.77
K_VCK
  Top 0.254: J11.34 52.06,10.76 76.96,10.76 82.73,16.54 85.15,16.54 U1.P$3
K_VIDH  (via drill 0.61)
  Top 0.406: 78.04,21.04 78.54,21.55 v78.54,24.6
  Top 0.61: 78.04,20.98 78.04,21.04 | R35.2 78.04,17.83 78.04,20.98 | AMP2.7 71.62,22 72.2,22.57 76.45,22.57 78.04,20.98 | 78.04,20.98 T6.P$1
  Bottom 0.254: RR3.P$2 87.03,34.46 87.88,33.62 87.88,31.97 87.77,31.86 CC3.P$7 87.77,28.2 88.13,27.84 88.13,27.77 89.02,27.77 89.28,27.52 89.28,26.38 88.7,25.81 81.21,25.81
  Bottom 0.305: v78.54,24.6 78.54,25.93 79.5,26.89 80.13,26.89 81.21,25.81
K_VIDL  (via drill 0.61)
  Top 0.406: T5.P$1 79.05,27.39 79.69,26.76 v79.69,25.81
  Top 0.61: 78.42,27.46 78.42,27.52 73.76,27.52 AMP2.1 | R32.2 77.38,33.68 79.24,33.68 79.94,32.98 79.94,28.79 78.61,27.46 78.42,27.46 | 78.42,27.46 T5.P$1
  Bottom 0.254: RR3.P$1 87.53,34.79 88.57,33.75 88.57,28.59 88.51,28.54 88.64,28.41 89.4,28.41 89.91,27.9 89.91,26.25 88.96,25.3 88.83,25.3
  Bottom 0.305: 88.58,28.6 88.57,28.59 CC3.P$8 | v79.69,25.81 80.2,25.3 88.83,25.3
K_VPL
  Top 0.254: J11.36 54.1,10.25 77.34,10.25 82.99,15.9 U1.P$4
K_VREF  (via drill 0.51 pad 0.3)
  Top 0.406: R7.1 83.81,41.74 R8.2 | R7.1 83.81,40.35 | R7.1 86.57,37.62 92.26,37.62 99.12,30.76 99.12,27.52 v99.18,27.46
  Bottom 0.406: 100.91,27.33 100.96,27.33 | 100.91,27.33 UOPT-CON.21 | v99.18,27.46 99.31,27.33 100.91,27.33
LCD_AC
  Bottom 0.254: J10.24 32.63,65.49 20.44,65.49 J10.12
LCDCLK
  Bottom 0.254: J10.21 30.09,59.91 25.52,59.91 J10.15
LD0
  Bottom 0.254: J10.33 42.29,56.86 13.33,56.86 J10.3
LD1
  Bottom 0.254: J10.4 11.3,66.51 41.78,66.51 J10.32
LD2
  Bottom 0.254: J10.31 40.25,57.37 15.36,57.37 J10.5
LD3
  Top 0.254: J10.6 13.84,66.51 38.98,66.51 41.52,63.97
  Top 0.406: 41.52,63.97 J10.30
LD4
  Bottom 0.254: J10.7 17.39,57.87 38.22,57.87 J10.29
LD5
  Top 0.254: J10.28 37.21,66 15.87,66 J10.8
LD6
  Bottom 0.254: J10.27 36.19,58.38 19.43,58.38 J10.9
LD7
  Bottom 0.254: J10.10 18.41,66 34.67,66 J10.26
LD8
  Bottom 0.254: J10.11 21.46,58.89 34.16,58.89 J10.25
N$1
  Top 0.61: TR4.2 42.67,33.62 R14.1
N$2
  Top 0.406: TR1.1 90.49,51.14 86.38,51.14 84.96,52.54 R22.1
N$3
  Top 0.406: 90.55,46.7 90.67,46.7 | TR2.1 90.49,46.7 90.55,46.7 | R23.1 85.21,49.24 87.75,46.7 90.55,46.7
N$4
  Top 0.406: TR3.1 88.84,42.25 84.96,46.19 R24.1
N$5  (via drill 0.61 pad 1.02)
  Top 0.406: v34.03,21.04 DAC.19 | C1.1 v18.92,21.04
  Bottom 0.406: v18.92,21.04 v34.03,21.04
N$6
  Top 0.406: R22.2 Q1.3
N$7  (via drill 0.61 pad 1.02)
  Top 0.406: C2.1 v16.38,28.41 | v34.16,26.12 DAC.23
  Bottom 0.406: v16.38,28.41 31.87,28.41 v34.16,26.12
N$8
  Top 0.61: R32.1 R29.2 73.88,30.8 71.62,28.54 AMP2.2
N$9
  Top 0.254: 0.25,63.21 0.25,67.65 5.71,67.65
N$10
  Top 0.254: 124.58,67.65 127.12,67.65 127.12,63.97
N$11
  Top 0.61: R30.1 49.91,16.95 49.91,16.85 46.42,16.85 TR6.2
N$12
  Top 0.61: AMP1.2 58.16,29.05 57.14,30.06 49.88,30.06 R16.1 R14.2
N$13
  Top 0.61: TR8.2 R10.1
N$14
  Top 0.61: DAC.17 34.67,18.5 C4.1
N$15
  Top 0.61: AMP2.6 70.25,20.51 70.23,20.54 70.23,19.52 71.5,18.25 74.35,18.25 74.86,17.74 R34.2 74.86,15.71 75.81,14.76 77.85,14.76 R35.1
N$16
  Top 0.61: R13.1 58.8,33.74 59.05,34 54.17,34 TR12.2
N$17
  Top 0.61: DAC.18 36.44,19.77 RBIAS.2
N$18
  Top 0.61: TR14.2 69.72,30.7 72.66,33.64 R29.1
N$19
  Top 0.61: TR13.2 72.13,12.03 74.1,12.03 74.86,12.92 R34.1
N$20
  Top 0.61: AMP1.6 56.89,19.14 56,18.25 56,16.85 R31.1
  Top 0.813: R30.2 R31.1
N$21
  Top 0.61: 18.92,42.25 R15.1 18.92,42.13 | 18.92,42.13 R20.2 | 15.38,43.27 15.36,43.27 | U3.1 15.38,43.27 | 18.92,42.13 17.77,43.27 15.38,43.27
N$22
  Top 0.254: 127.12,3.77 127.12,0.22 123.57,0.22
N$23
  Top 0.254: 3.17,0.22 0.25,0.22 0.25,4.53
N$25
  Top 0.406: 75.03,57.24 75.18,57.24 | 75.03,57.24 Q1.1 | R28.1 75.03,57.24
N$26
  Top 0.254: R19.2 108.45,60.67 108.53,60.74 L2.P$2
N$27
  Top 0.254: L3.P$2 114.24,62.39 112.52,60.67
  Top 0.406: R21.2 112.64,60.67 112.52,60.67
N$28
  Top 0.254: R27.2 119.88,60.67 119.96,60.74 L4.P$2
N$31
  Top 0.406: 72.13,53.43 R33.1 73.76,53.43 Q2.1
N$34
  Top 0.406: 72.16,49.85 72.13,49.87 | R36.1 72.16,49.85 | Q3.1 74.86,47.14 72.16,49.85
N$36  (via drill 0.61 pad 1.02)
  Top 0.61: v26.03,46.82 MAX762.3 | R1.1 R2.2 v38.48,46.82
  Bottom 0.61: v26.03,46.82 v38.48,46.82
N$37  (1 unrouted)
  Top 0.61: D1.2 6.22,38.53 6.22,53.05 11.04,57.87 23.62,57.87 24.76,56.73 MAX762.7
N$38
  Top 0.61: MAX762.5 27.3,55.21 29.08,55.21 C5.2
N$47
  Top 0.406: 81.02,49.24 R23.2 79.2,49.24 Q2.3
N$49
  Top 0.406: Q3.3 R24.2
PDR
  Bottom 0.254: RR3.P$13 86.03,37.17 87.37,38.51 98.48,38.51 101.34,41.36 104.9,41.36 106.8,39.46 106.8,37.36 106.29,36.86 105.59,36.86 105.55,36.87 UOPT-CON.2
RENE
  Bottom 0.254: RR1.P$15 98.5,12.43 100.9,14.82 100.9,17.42 98.04,20.28 98.04,23.2 99.18,24.35 100.33,24.35
  Bottom 0.305: 100.33,24.35 100.3,24.37 UOPT-CON.27
RENO
  Bottom 0.254: RR1.P$16 98.77,11.93 101.4,14.57 101.4,17.68 98.55,20.54 98.55,22.76 99.12,23.33 | 99.12,23.33 100.26,23.33 | 99.12,23.33 99.06,23.33
  Bottom 0.305: 100.3,23.37 100.33,23.39 | 100.3,23.37 UOPT-CON.29 | 100.26,23.33 100.3,23.37
RSRX1  (via drill 0.61)
  Top 0.254: v107.82,7.71 107.82,3.77 109.09,2.5 112.77,2.5 124.84,14.57 124.84,40.6 125.6,41.36 125.6,43.4 124.58,44.41 122.8,44.41 121.79,45.43 121.79,47.21 RS232-1.1 | v47.11,10.88 46.98,10.88 46.73,11.14 39.75,11.14 v38.98,11.9
  Bottom 0.254: v107.82,7.71 107.18,8.34 49.65,8.34 v47.11,10.88 | v38.98,11.9 38.48,12.41 33.4,12.41 32.89,11.9 29.33,11.9 25.78,8.34 22.73,8.34 21.71,7.33 20.7,7.33 J11.12
RSRX2  (via drill 0.61)
  Top 0.254: RS232-2.1 123.31,41.87 123.31,14.95 111.88,3.52 110.48,3.52 110.1,3.9 v110.1,5.42 | v44.83,8.85 43.56,10.12 36.7,10.12 v35.94,10.88
  Bottom 0.254: v110.1,5.42 108.07,5.42 106.17,7.33 46.35,7.33 v44.83,8.85 | v35.94,10.88 35.43,11.39 33.9,11.39 33.4,10.88 29.84,10.88 26.28,7.33 23.24,7.33 J11.14
RSTX1  (via drill 0.61)
  Top 0.254: RS232-1.2 121.28,44.92 122.3,43.9 124.33,43.9 125.09,43.14 125.09,41.62 124.2,40.73 124.07,40.73 124.07,14.82 112.26,3.01 109.98,3.01 108.96,4.03 v108.96,6.57 | v45.97,9.87 45.21,10.63 38.22,10.63 v37.46,11.39
  Bottom 0.254: v108.96,6.57 107.69,6.57 106.42,7.84 48,7.84 v45.97,9.87 | v37.46,11.39 36.95,11.9 33.65,11.9 33.14,11.39 29.59,11.39 26.03,7.84 22.98,7.84 21.97,6.82 20.95,6.82 20.19,6.06 20.19,4.28 J11.11 18.92,2.88
RSTX2  (via drill 0.61)
  Top 0.254: RS232-2.2 122.55,41.11 122.55,15.2 111.76,4.41 v111.25,4.41 | v43.81,7.84 43.3,7.84 41.52,9.61 35.17,9.61 v34.41,10.38
  Bottom 0.254: v111.25,4.41 108.2,4.41 105.79,6.82 44.7,6.82 v43.81,7.84 | v34.41,10.38 30.09,10.38 26.54,6.82 23.49,6.82 22.73,6.06 22.73,4.03 21.71,3.01 J11.13
RX+
  Top 0.254: J11.63 86.48,4.28 102.23,4.28 109.09,11.14 109.09,13.17 109.98,14.06 ETHERNET.3
RX-
  Top 0.254: J11.65 88.26,3.77 102.61,3.77 109.09,10.25 ETHERNET.6
SENSE1  (via drill 0.51 pad 1.02)
  Top 0.254: v107.56,47.21 105.79,48.98 105.79,51.02 98.42,58.38 76.58,58.38 74.8,60.16 J10.55
  Bottom 0.254: v107.56,47.21 114.17,47.21 RS232-1.4
SENSE2  (via drill 0.51 pad 1.02)
  Top 0.254: J10.53 72.77,61.43 76.32,57.87 98.17,57.87 104.77,51.27 104.77,48.48 v108.58,44.67
  Bottom 0.254: v108.58,44.67 113.91,44.67 RS232-2.4
TEST1
  Bottom 0.254: UOPT-CON.30 106.72,22.87 109.28,25.43 109.28,39.97 105.53,43.71 100.83,43.71 97.91,40.79 86.67,40.79 84.01,38.12 84.01,36.28 RR3.P$9
TEST2
  Bottom 0.254: RR3.P$10 84.53,37.95 86.86,40.28 98.1,40.28 101.02,43.21 105.28,43.21 108.77,39.71 108.77,26.06 106.61,23.9 105.41,23.9 UOPT-CON.28 | UOPT-CON.28 105.34,23.84 | UOPT-CON.28
TEST3
  Bottom 0.254: UOPT-CON.24 106.42,25.87 108.26,27.71 108.26,39.52 105.15,42.63 101.15,42.63 98.23,39.71 87.05,39.71 85.02,37.68 85.02,36.28 RR3.P$11
TEST4
  Bottom 0.254: RR3.P$12 85.53,37.43 87.31,39.2 98.42,39.2 101.34,42.13 104.9,42.13 107.76,39.27 107.76,28.28 106.42,26.89 105.28,26.89 105.29,26.87 UOPT-CON.22
TX+
  Top 0.254: J11.64 86.61,7.2 100.58,7.2 110.48,17.11 113.28,17.11 ETHERNET.1
TX-
  Top 0.254: ETHERNET.2 109.72,15.33 99.94,5.55 J11.66
TX/RX  (via drill 0.51 pad 0.3)
  Top 0.254: v81.02,15.96 81.21,16.16 81.66,16.16 82.67,17.17 U1.P$2 | v80.26,17.55 80.26,18 80.7,18.44 80.7,22.12 82.3,23.72 U2.P$2
  Bottom 0.254: J11.15 25.27,4.28 27.3,4.28 27.81,4.79 27.81,6.82 29.33,8.34 37.21,8.34 38.22,9.36 41.02,9.36 45.59,13.93 48.89,13.93 51.94,10.88 77.08,10.88 81.02,14.82 v81.02,15.96 80.26,16.73 v80.26,17.55
USBD+  (via drill 0.61 pad 1.02)
  Top 0.254: USB.3 115.95,32.98 | 115.95,32.98 115.95,36.28 111.63,40.6 111.63,50.25 113.53,52.16 115.69,52.16 v116.45,52.92 | RUSB2.2 116.2,32.73 115.95,32.98
  Bottom 0.254: J11.59 81.91,0.98 114.8,0.98 117.47,3.64 117.47,18.63 112.64,23.46 112.64,29.68 USB.3 | v116.45,52.92 116.84,53.3 116.84,61.05 116.71,61.18 116.76,61.22 BODY-BUS.P$3
USBD-  (via drill 0.61 pad 1.02)
  Top 0.254: USB.2 113.91,32.98 | 113.91,32.98 115.18,34.25 115.18,36.03 110.87,40.35 110.87,51.02 113.15,53.3 v114.93,53.3 | RUSB1.2 114.68,29.93 114.17,29.43 113.66,29.43 112.64,30.44 112.64,31.71 113.91,32.98
  Bottom 0.254: J11.60 81.15,4.28 97.91,4.28 100.33,1.74 114.17,1.74 116.71,4.28 116.71,18.25 111.88,23.33 111.88,30.95 USB.2 | BODY-BUS.P$4 116.07,61.18 116.07,59.02 116.2,58.89 116.2,54.57 v114.93,53.3
VCK
  Bottom 0.254: RR1.P$9 97,15.43 97.59,16.03 97.59,16.34 94.93,19.01 94.93,31.84 98.48,35.39 100.32,35.39 | 100.32,35.39 100.33,35.39 | 100.32,35.39 UOPT-CON.5
VIDH
  Bottom 0.254: UOPT-CON.3 98.7,36.37 94.23,31.9 94.23,28.79 93.85,28.41 91.82,28.41 91.05,29.17 91.05,35.46 89.09,37.43 87.81,37.43 87.05,36.73 87.05,36.35 87.03,36.33 RR3.P$15
VIDL  (via drill 0.51 pad 0.3)
  Top 0.254: v93.78,22.38 v99.37,22.38
  Bottom 0.254: RR3.P$16 87.53,36.45 88.01,36.92 88.83,36.92 90.48,35.27 90.48,25.68 v93.78,22.38 | UOPT-CON.31 99.38,22.37 v99.37,22.38
VOUT1
  Top 0.254: T1.P$1 59.56,28.41 59.56,26.66 | 59.56,26.66 59.56,26.63 | AMP1.1 59.56,26.66
  Top 0.61: AMP1.1 R17.2 52.57,31.2 50.19,33.62 R16.2
VOUT2
  Top 0.254: 58.03,19.01 58.16,19.01 58.29,19.01 58.54,18.76 T2.P$1 60.83,18.76
  Top 0.61: AMP1.7 58.16,19.01 58.8,18.38 58.8,16.85 R31.2 R11.2
VOUT_HI
  Top 0.254: 66.67,18.25 65.91,19.01 65.65,19.01 T3.P$1
  Top 0.61: 65.17,16.75 R11.1 | 65.17,16.75 66.67,18.25 68.96,20.54 | 68.96,20.54 69.08,20.66 | AMP2.5 68.98,20.51 68.96,20.54 | 65.02,13.58 65.02,13.55 | R9.1 65.02,13.58 | 65.17,16.75 65.02,16.6 65.02,13.58
  Top 0.813: R10.2 R9.1
VOUT_LOW
  Top 0.254: T4.P$1 64.64,29.68
  Top 0.61: R12.1 62.22,34.12 R13.2 62.22,32.73 R17.1 62.35,31.1 62.35,30.19 62.86,29.68 64.64,29.68 68.19,29.68 70.35,27.52 AMP2.3
VPL
  Bottom 0.254: RR1.P$10 97.19,14.93 98.29,16.03 98.29,16.41 95.44,19.27 95.44,31.59 98.17,34.31 100.2,34.31 100.26,34.38 100.27,34.37 UOPT-CON.7
VSYNC
  Bottom 0.254: J10.23 32.13,59.4 23.49,59.4 J10.13

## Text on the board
Top: component | MIThril BSE dock v1000-6 31/08/2001
Bottom: Copyright (C) 2001 MIT Media Lab | IHTFP | R. W. DeVaul | EVILB0RG
tPlace: T11 | T12 | MIThril BSE dock v1000-6 31/08/2001 | <borglab> | Richard W. DeVaul | T22 | Copyright (C) 2001, MIT | T21 | MIThril@media.mit.edu | http://www.media.mit.edu/wearables/mithril/
bPlace: uOpt. Cable | Copyright (C) 2001 MIT Media Lab | strain relief | IHTFP | MIThril | BSE dock | v1000-6 | EVILB0RG | <borglab> | MIThril@media.mit.edu
Reference: BSE length: 3.4 in | 0.100 | 3.1 | 0.150 | 1.85 | BSE width: 2.6 in | 0.100 | 0.375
